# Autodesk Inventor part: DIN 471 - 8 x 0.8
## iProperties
Comments: To add or edit properties for Autodesk Inventor files, use iProperties.
Created: 2003-08
Part Number: DIN 471 - 8 x 0.8
Vendor: Autodesk Inc.
Document SubType Name: Modeling
Designer: FranzK
Material: Default
Description: Spring Retaining Ring
Standard: DIN 471
Manufacturer: Standard
Standards Organization: Custom
Alert: To add or edit properties for Autodesk Inventor files, use iProperties.
Control State: 0
Master: False
Checked Out: False
Shininess: 64.0
Length Units: 11269
Angle Units: 11279
Time Units: 11290
Mass Units: 11283
Length Display Precision: 3
Angle Display Precision: 2
Compacted: True
Density: 0.0
Volumn: 0.0
Area: 0.0
PropertySet Name: Model Information
Author: FranzK
Revision Number: 5
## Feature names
1. Body [Extrusion]
